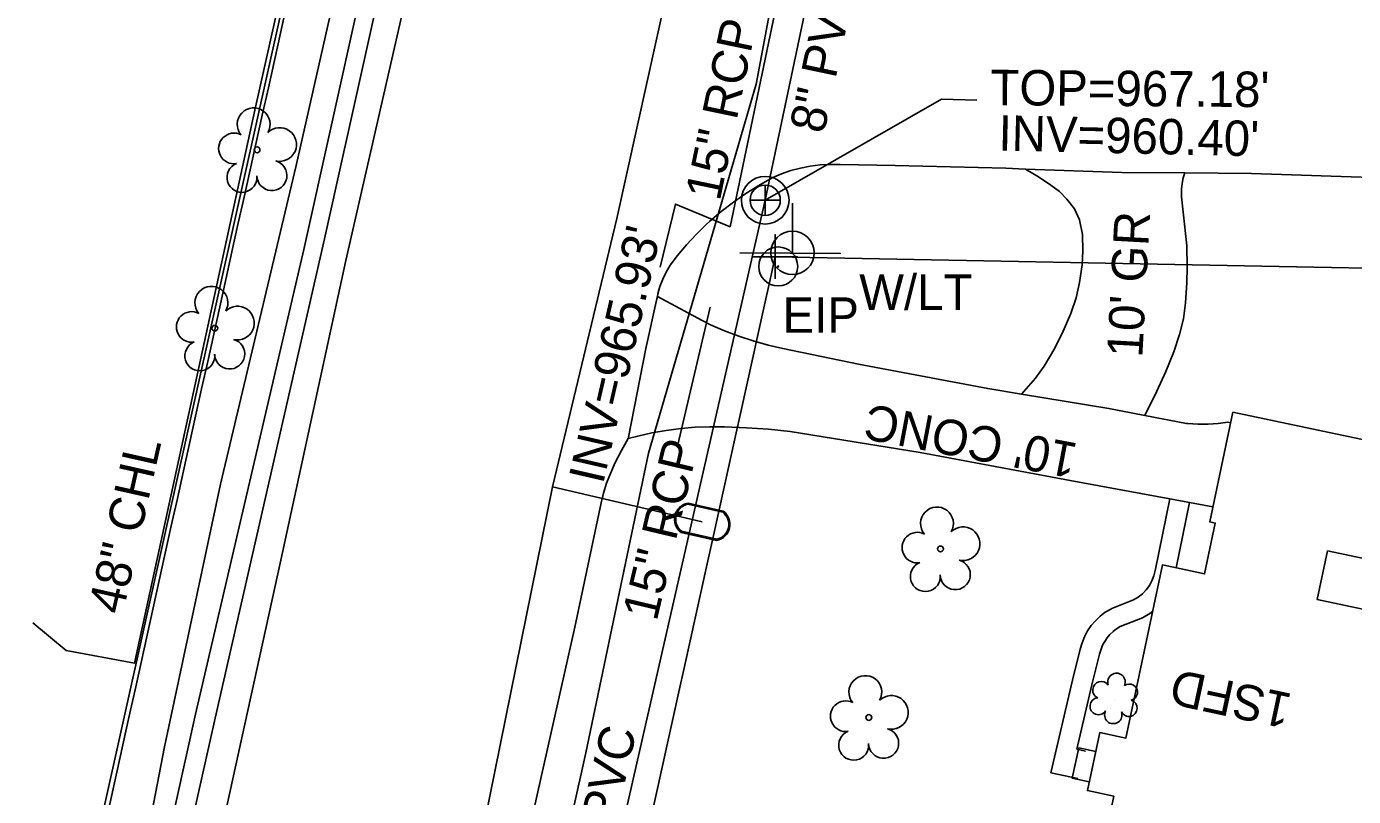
# Model space of a CAD drawing. Extents: x 1614611 to 1617571, y 898867 to 905462.
# Drawn here: x 1616262.4 to 1616412.2, y 900159.4 to 900246.3 of the extents above; entities that cross this region are included whole.
import ezdxf

# ---------------------------------------------------------------- set-up
doc = ezdxf.new("R2010")
doc.units = 0
for name, color, linetype in [('Exist Building', 7, 'Continuous'), ('Exist Building Text', 7, 'Continuous'), ('Exist Drainage Structure Drop Inlet CELL', 7, 'Continuous'), ('Exist Other Culture Area Outline', 7, 'Continuous'), ('Exist Other Culture Fence Line', 7, 'Continuous'), ('Exist Other Culture Fence Line Text', 7, 'Continuous'), ('Exist Other Culture Gate', 7, 'Continuous'), ('Exist Plan Preparation Watershed Yellow', 7, 'Continuous'), ('Exist Roads EOP Other Text', 7, 'Continuous'), ('Exist Roads Soil', 7, 'Continuous'), ('Exist Structure Minor Pipes RCP 15 Inch Invert', 7, 'Continuous'), ('Exist Utilities Gas UG Line SUE LOS B', 7, 'Continuous'), ('Exist Utilities Power Joint Use Telephone CELL', 7, 'Continuous'), ('Exist Utilities Power Pole Text', 7, 'Continuous'), ('Exist Utilities Sanitary Sewer AG Line Leader', 7, 'Continuous'), ('Exist Utilities Sanitary Sewer Manhole Text', 7, 'Continuous'), ('Exist Utilities Sanitary Sewer UG Line', 7, 'Continuous'), ('Exist Utilities Sanitary Sewer UG Line Invert Elevation', 7, 'Continuous'), ('Exist Utilities Sanitary Sewer UG Line Text', 7, 'Continuous'), ('Exist Utilities Telephone UG Cable SUE LOS B', 7, 'Continuous'), ('Exist Utilities Telephone UG Cable SUE LOS C', 7, 'Continuous'), ('Exist Utilities Telephone UG FO SUE LOS B', 7, 'Continuous'), ('Exist Utilities Telephone UG FO SUE LOS C', 7, 'Continuous'), ('Exist Utilities Water UG Line SUE LOS B', 7, 'Continuous'), ('Exist Vegetation Shrub CELL', 7, 'Continuous'), ('Exist Vegetation Tree CELL', 7, 'Continuous'), ('Old_Level_21', 7, 'Continuous'), ('Prop Drainage Structure Removal Label', 7, 'Continuous'), ('Prop Drainage Structure Tops and Inverts LABEL', 7, 'Continuous'), ('Prop Earthen Structure Head Ditch Label', 7, 'Continuous'), ('Prop Erosion Embankment Toe Protection with Rip Rap 2 Detail CELL', 7, 'Continuous'), ('Prop Plan Preparation Table Ditch Data CELL', 7, 'Continuous'), ('Prop SS Transition Line', 7, 'Continuous'), ('Scratch_Level_1', 7, 'Continuous'), ('Scratch_Level_9', 7, 'Continuous')]:
    doc.layers.add(name, color=color, linetype=linetype)

msp = doc.modelspace()

# ---------------------------------------------------------------- linework, layer by layer
at = {"layer": 'Exist Building'}
msp.add_lwpolyline([(1616398.62, 900202.81), (1616417.87, 900198.75), (1616415.15, 900185.89), (1616409.3, 900187.13), (1616408.14, 900181.65), (1616420.19, 900179.11), (1616414.27, 900151.09), (1616398.7, 900154.38), (1616397.06, 900146.63), (1616383.08, 900149.58), (1616385.16, 900159.46), (1616382.19, 900160.08), (1616383.58, 900166.63), (1616386.53, 900166.01), (1616390.66, 900185.56), (1616395.42, 900184.55), (1616396.63, 900190.28), (1616396, 900190.41)], close=True, dxfattribs=at)
at = {"layer": 'Exist Other Culture Area Outline'}
for points in [[(1616381.12, 900161.46), (1616378.07, 900162.09), (1616380.51, 900172.56), (1616381.39, 900176.06), (1616381.59, 900176.77), (1616381.86, 900177.45), (1616382.21, 900178.1), (1616382.62, 900178.7), (1616383.09, 900179.26), (1616383.63, 900179.77), (1616384.21, 900180.21), (1616384.84, 900180.58), (1616384.94, 900180.63), (1616387.41, 900181.6), (1616387.93, 900181.92), (1616388.41, 900182.3), (1616388.83, 900182.73), (1616389.19, 900183.22), (1616389.48, 900183.76), (1616389.7, 900184.32), (1616389.84, 900184.91), (1616389.87, 900185.06), (1616391.49, 900193.01)], [(1616392.2, 900185.23), (1616393.7, 900192.6)], [(1616381.97, 900164.54), (1616381.01, 900164.76), (1616382.7, 900172.03), (1616383.57, 900175.49), (1616383.73, 900176.05), (1616383.91, 900176.5), (1616384.14, 900176.93), (1616384.41, 900177.34), (1616384.73, 900177.71), (1616385.08, 900178.04), (1616385.47, 900178.33), (1616385.89, 900178.59), (1616388.41, 900179.57), (1616389.22, 900180.06), (1616389.56, 900180.34)], [(1616382.4, 900161.06), (1616380.48, 900161.48), (1616381.23, 900164.92), (1616383.13, 900164.51)]]:
    msp.add_lwpolyline(points, dxfattribs=at)
at = {"layer": 'Exist Other Culture Fence Line'}
msp.add_lwpolyline([(1616185.76, 900206.96), (1616171.64, 900210.69), (1616180.06, 900246.24), (1616199.38, 900333.73), (1616261.08, 900334.91), (1616309.42, 900336), (1616298.22, 900281.63), (1616288.21, 900236.88), (1616274.6, 900174.45), (1616266.9, 900175.88)], dxfattribs=at)
at = {"layer": 'Exist Other Culture Gate'}
msp.add_line((1616266.9, 900175.88), (1616263.14, 900179.03), dxfattribs=at)
at = {"layer": 'Exist Plan Preparation Watershed Yellow'}
for radius in [2.2, 0.0707]:
    msp.add_circle((1616347.28, 900219.25), radius, dxfattribs=at)
at = {"layer": 'Exist Roads Soil'}
for points in [[(1616374.75, 900204.84), (1616376.31, 900206.65), (1616377.3, 900208.01), (1616378.5, 900210.02), (1616379.44, 900211.93), (1616380.31, 900213.92), (1616380.92, 900215.69), (1616381.31, 900217.42), (1616381.58, 900219.45), (1616381.67, 900221.02), (1616381.62, 900222.87), (1616381.28, 900224.5), (1616380.73, 900225.74), (1616379.86, 900226.86), (1616379.02, 900227.7), (1616378.06, 900228.43), (1616376.67, 900229.35), (1616375.2, 900230.25)], [(1616388.66, 900202.44), (1616390.03, 900205.18), (1616391.06, 900207.38), (1616391.96, 900209.6), (1616392.59, 900211.55), (1616393.02, 900213.35), (1616393.26, 900215.13), (1616393.41, 900217.39), (1616393.45, 900219.16), (1616393.43, 900221.6), (1616393.01, 900225.37), (1616392.81, 900227.1), (1616392.8, 900227.96), (1616392.87, 900228.61), (1616392.99, 900229.25), (1616393.2, 900229.8)]]:
    msp.add_lwpolyline(points, dxfattribs=at)
at = {"layer": 'Exist Utilities Gas UG Line SUE LOS B'}
msp.add_lwpolyline([(1616228.95, 899933.49), (1616238.93, 899978.7), (1616250.88, 900021.2), (1616259.71, 900057.93), (1616268.22, 900097.82), (1616270.1, 900108.73), (1616270.66, 900110.37), (1616273.78, 900123.94), (1616283.72, 900168.25), (1616296.04, 900222.38), (1616305.4, 900264.37), (1616315.91, 900311.24), (1616322.64, 900340.02), (1616331.7, 900383.47)], dxfattribs=at)
at = {"layer": 'Exist Utilities Power Joint Use Telephone CELL'}
msp.add_line((1616348.88, 900220.77), (1616348.88, 900220.77), dxfattribs=at)
msp.add_lwpolyline([(1616342.95, 900220.77), (1616354.28, 900220.73), (1616348.88, 900220.75), (1616348.88, 900226.39)], dxfattribs=at)
msp.add_circle((1616348.89, 900220.78), 2.45, dxfattribs=at)
at = {"layer": 'Exist Utilities Sanitary Sewer AG Line Leader'}
msp.add_lwpolyline([(1616345.82, 900226.73), (1616365.72, 900238.14), (1616369.69, 900238.01)], dxfattribs=at)
at = {"layer": 'Exist Utilities Sanitary Sewer UG Line'}
msp.add_lwpolyline([(1616305.43, 900049.6), (1616345.82, 900226.73), (1616377.74, 900378.04)], dxfattribs=at)
at = {"layer": 'Exist Utilities Telephone UG Cable SUE LOS B'}
msp.add_lwpolyline([(1616244.2, 900051.3), (1616247.08, 900051.95), (1616254.34, 900051.12), (1616261.35, 900056.95), (1616270.62, 900097.78), (1616272.63, 900108.4), (1616271.69, 900124.33), (1616281.5, 900168.7), (1616293.72, 900221.15), (1616303.1, 900263.43), (1616314, 900311.75), (1616319.02, 900336.01), (1616313.74, 900338.14), (1616311.89, 900339.38)], dxfattribs=at)
at = {"layer": 'Exist Utilities Telephone UG Cable SUE LOS C'}
msp.add_lwpolyline([(1616244.2, 900051.3), (1616248.43, 900052.69), (1616253.12, 900054.18), (1616256.06, 900055.79), (1616257.99, 900061.57), (1616266.68, 900088.03), (1616271.15, 900108.67), (1616270.12, 900124.07), (1616271.06, 900129.11), (1616277.99, 900165.03), (1616284.33, 900194.68), (1616292.87, 900230.63), (1616300.4, 900263.94), (1616307.49, 900293.65), (1616316.18, 900332.48), (1616316.31, 900333.6), (1616315.2, 900335.07), (1616313.08, 900336.87), (1616311.89, 900339.38)], dxfattribs=at)
at = {"layer": 'Exist Utilities Telephone UG FO SUE LOS B'}
msp.add_lwpolyline([(1616264.27, 899888.11), (1616275.63, 899938.03), (1616283.17, 899975.46), (1616294.6, 900026.16), (1616305.05, 900073.25), (1616315.15, 900117.57), (1616325.55, 900164.34), (1616332.62, 900198.17), (1616344.78, 900239.81), (1616353.34, 900285.35), (1616361.31, 900327.32), (1616372.74, 900375.18)], dxfattribs=at)
at = {"layer": 'Exist Utilities Telephone UG FO SUE LOS C'}
msp.add_line((1616246.03, 900045.13), (1616403.99, 900755.27), dxfattribs=at)
at = {"layer": 'Exist Utilities Water UG Line SUE LOS B'}
msp.add_line((1616321.8, 900194.38), (1616338.71, 900190.42), dxfattribs=at)
msp.add_lwpolyline([(1616263.66, 899921.5), (1616269.73, 899949.09), (1616273.73, 899969.37), (1616281.36, 900005.29), (1616288.43, 900036.76), (1616298.97, 900086.16), (1616304.15, 900111.94), (1616312.34, 900147.74), (1616321.8, 900194.38), (1616329.08, 900224.67), (1616335.91, 900255.64), (1616338.25, 900266.44), (1616344.58, 900294.92), (1616354.08, 900334.27), (1616364.03, 900380.59)], dxfattribs=at)
at = {"layer": 'Exist Vegetation Shrub CELL'}
msp.add_line((1616385.24, 900170.31), (1616385.24, 900170.31), dxfattribs=at)
for centre, radius, start, end in [((1616385.47, 900172.35), 0.99, 334.8391, 200.4717), ((1616383.76, 900171.43), 0.968, 35.8908, 245.4216), ((1616386.91, 900171.18), 0.929, 284.4567, 126.0861), ((1616383.44, 900169.6), 0.955, 95.1099, 327.9534), ((1616386.88, 900169.38), 0.937, 204.9913, 73.4601), ((1616385.11, 900168.62), 0.984, 151.2797, 21.387)]:
    msp.add_arc(centre, radius, start, end, dxfattribs=at)
at = {"layer": 'Exist Vegetation Tree CELL'}
for p, q in [((1616288.45, 900232.42), (1616288.45, 900232.42)), ((1616283.68, 900212.27), (1616283.68, 900212.27)), ((1616365.6, 900187.36), (1616365.6, 900187.36)), ((1616357.51, 900168.33), (1616357.51, 900168.33))]:
    msp.add_line(p, q, dxfattribs=at)
for centre in [(1616288.45, 900232.42), (1616283.68, 900212.27), (1616365.6, 900187.36), (1616357.51, 900168.33)]:
    msp.add_circle(centre, 0.326, dxfattribs=at)
for centre, radius, start, end in [((1616288.06, 900235.29), 1.86, 330.1651, 219.7134), ((1616291, 900233.01), 1.9, 257.1011, 134.1999), ((1616285.84, 900232.57), 1.73, 62.6636, 279.3457), ((1616286.74, 900229.3), 1.69, 111.5671, 6.231), ((1616290.12, 900229.52), 1.7, 181.2822, 74.56), ((1616283.29, 900215.14), 1.86, 330.1651, 219.7134), ((1616281.07, 900212.42), 1.73, 62.6636, 279.3457), ((1616286.23, 900212.86), 1.9, 257.1011, 134.1999), ((1616281.98, 900209.15), 1.69, 111.5671, 6.231), ((1616285.35, 900209.37), 1.7, 181.2822, 74.56), ((1616365.21, 900190.23), 1.86, 330.1651, 219.7134), ((1616368.15, 900187.95), 1.9, 257.1011, 134.1999), ((1616362.99, 900187.51), 1.73, 62.6636, 279.3457), ((1616363.89, 900184.24), 1.69, 111.5671, 6.231), ((1616367.27, 900184.46), 1.7, 181.2822, 74.56), ((1616357.12, 900171.2), 1.86, 330.1651, 219.7134), ((1616354.9, 900168.48), 1.73, 62.6636, 279.3457), ((1616360.06, 900168.91), 1.9, 257.1011, 134.1999), ((1616359.18, 900165.43), 1.7, 181.2822, 74.56), ((1616355.8, 900165.2), 1.69, 111.5671, 6.231)]:
    msp.add_arc(centre, radius, start, end, dxfattribs=at)
at = {"layer": 'Old_Level_21'}
msp.add_lwpolyline([(1616345.81, 900228.44), (1616345.81, 900225.02), (1616345.81, 900226.73), (1616347.52, 900226.73), (1616344.09, 900226.73)], dxfattribs=at)
for radius in [2.69, 1.71]:
    msp.add_circle((1616345.81, 900226.73), radius, dxfattribs=at)
at = {"layer": 'Prop Drainage Structure Removal Label'}
msp.add_lwpolyline([(1616341.86, 900223.71), (1616335.68, 900226.29), (1616333.94, 900219.17)], dxfattribs=at)
at = {"layer": 'Prop Drainage Structure Tops and Inverts LABEL'}
msp.add_line((1616346.95, 900220.35), (1616346.95, 900220.35), dxfattribs=at)
msp.add_lwpolyline([(1616344.45, 900220.35), (1616349.45, 900220.35), (1616346.95, 900220.35), (1616346.95, 900222.85), (1616346.95, 900217.85)], dxfattribs=at)
at = {"layer": 'Prop Earthen Structure Head Ditch Label'}
msp.add_line((1616346.95, 900220.35), (1616622.33, 900214.99), dxfattribs=at)
for radius, start, end in [(100030, 167.4537079, 167.5697278), (99970, 167.4989737, 167.7161189)]:
    msp.add_arc((1713946.87, 878581.13), radius, start, end, dxfattribs=at)
at = {"layer": 'Prop Plan Preparation Table Ditch Data CELL'}
for p, q in [((1616349.29, 900259.43), (1616341.86, 900223.71)), ((1616339.61, 900214.66), (1616335.9, 900198.98))]:
    msp.add_line(p, q, dxfattribs=at)
at = {"layer": 'Prop SS Transition Line'}
msp.add_line((1616338.71, 900190.42), (1616338.71, 900190.42), dxfattribs=at)
for points in [[(1616337.1, 900192.53), (1616341.07, 900191.63)], [(1616337.07, 900192.4), (1616341.04, 900191.5)], [(1616340.32, 900188.32), (1616336.32, 900189.22)], [(1616340.35, 900188.45), (1616336.35, 900189.36)]]:
    msp.add_lwpolyline(points, dxfattribs=at)
for centre, radius, start, end in [((1616337.43, 900190.71), 1.86, 100.4278, 233.2292), ((1616337.44, 900190.71), 1.73, 102.5507, 231.0321), ((1616339.97, 900190.14), 1.86, 280.8981, 53.5581), ((1616339.98, 900190.14), 1.73, 282.3769, 52.1226)]:
    msp.add_arc(centre, radius, start, end, dxfattribs=at)
at = {"layer": 'Scratch_Level_1'}
for points in [[(1616398.37, 900201.6), (1616398.06, 900201.67), (1616396.94, 900201.51), (1616395.81, 900201.43), (1616394.67, 900201.43), (1616393.54, 900201.51), (1616393.36, 900201.53), (1616388.66, 900202.44), (1616384.61, 900203.23), (1616374.75, 900204.84), (1616370.94, 900205.46), (1616356.35, 900208.23), (1616347.8, 900210), (1616346.13, 900210.38), (1616344.47, 900210.84), (1616342.83, 900211.38), (1616341.22, 900211.99), (1616339.65, 900212.67), (1616338.68, 900213.13), (1616333.64, 900215.87)], [(1616396.36, 900192.1), (1616393.7, 900192.6), (1616391.49, 900193.01), (1616380.26, 900195.09), (1616363.29, 900198.25), (1616348.64, 900200.62), (1616346.18, 900200.87), (1616343.71, 900201.05), (1616341.23, 900201.14), (1616339.56, 900201.16), (1616337.92, 900201.09), (1616336.28, 900200.95), (1616334.65, 900200.73), (1616333.02, 900200.45), (1616331.42, 900200.1), (1616330.34, 900199.82)]]:
    msp.add_lwpolyline(points, dxfattribs=at)
at = {"layer": 'Scratch_Level_9'}
for points in [[(1616277.78, 900124.91), (1616283.67, 900152.17), (1616291.12, 900186.08), (1616298.45, 900219.92), (1616305.64, 900251.41), (1616313.34, 900285.67), (1616320.34, 900318.08), (1616327.24, 900348.71), (1616334.4, 900380.72), (1616342.13, 900414.51), (1616348.75, 900444.16), (1616354.62, 900470.67), (1616359.82, 900493.8), (1616362.54, 900506.97)], [(1616415.37, 900229.27), (1616400.73, 900229.73), (1616393.2, 900229.8), (1616386.06, 900229.87), (1616375.2, 900230.25), (1616372.98, 900230.33), (1616360.5, 900230.63), (1616354.27, 900230.75), (1616353.15, 900230.77), (1616352.02, 900230.71), (1616350.9, 900230.58), (1616349.8, 900230.36), (1616348.71, 900230.07), (1616347.64, 900229.7), (1616346.6, 900229.25), (1616346.6, 900229.25), (1616345.1, 900228.4), (1616343.64, 900227.48), (1616342.22, 900226.49), (1616340.85, 900225.44), (1616339.53, 900224.33), (1616339.15, 900223.99), (1616338.02, 900222.87), (1616336.94, 900221.7), (1616335.91, 900220.47), (1616335.09, 900219.38), (1616334.63, 900218.62), (1616334.25, 900217.83), (1616333.93, 900217), (1616333.69, 900216.14), (1616333.64, 900215.87), (1616333.59, 900215.6), (1616332.33, 900210), (1616330.37, 900199.99), (1616330.34, 900199.82), (1616329.58, 900198.49), (1616328.89, 900197.13), (1616328.34, 900195.89), (1616327.91, 900194.78), (1616327.55, 900193.64), (1616327.28, 900192.57), (1616324.33, 900178.53), (1616318.14, 900151.05)]]:
    msp.add_lwpolyline(points, dxfattribs=at)

# ---------------------------------------------------------------- texts
at = {"layer": 'Exist Building Text'}
msp.add_text('1SFD', height=4, rotation=167.9641, dxfattribs=at).set_placement((1616405.46, 900170.96))
at = {"layer": 'Exist Drainage Structure Drop Inlet CELL'}
msp.add_text('EIP', height=4, dxfattribs=at).set_placement((1616347.77, 900211.76))
at = {"layer": 'Exist Other Culture Fence Line Text'}
msp.add_text('48" CHL', height=4, rotation=77.3347, dxfattribs=at).set_placement((1616273.26, 900179.84))
at = {"layer": 'Exist Roads EOP Other Text'}
for s, rotation, p in [("10' GR", 86.88, (1616388.38, 900208.9)), ("10' CONC", 169.2367, (1616381.26, 900199.23))]:
    msp.add_text(s, height=4, rotation=rotation, dxfattribs=at).set_placement(p)
at = {"layer": 'Exist Structure Minor Pipes RCP 15 Inch Invert'}
msp.add_text("INV=965.93'", height=4, rotation=77.0124, dxfattribs=at).set_placement((1616327.5, 900194.56))
at = {"layer": 'Exist Utilities Power Pole Text'}
msp.add_text('W/LT', height=4, dxfattribs=at).set_placement((1616356.43, 900214.35))
at = {"layer": 'Exist Utilities Sanitary Sewer Manhole Text'}
msp.add_text("TOP=967.18'", height=4, rotation=359.5785, dxfattribs=at).set_placement((1616371.23, 900237.46))
at = {"layer": 'Exist Utilities Sanitary Sewer UG Line Invert Elevation'}
msp.add_text("INV=960.40'", height=4, rotation=358.6965, dxfattribs=at).set_placement((1616372.12, 900232.34))
at = {"layer": 'Exist Utilities Sanitary Sewer UG Line Text'}
for rotation, p in [(78.0873, (1616352.44, 900234.12)), (77.1562, (1616327.46, 900149.93))]:
    msp.add_text('8" PVC', height=4, rotation=rotation, dxfattribs=at).set_placement(p)
at = {"layer": 'Prop Erosion Embankment Toe Protection with Rip Rap 2 Detail CELL'}
for rotation, p in [(78.2456, (1616340.68, 900226.53)), (76.6625, (1616333.55, 900179.1))]:
    msp.add_text('15" RCP', height=4, rotation=rotation, dxfattribs=at).set_placement(p)

doc.saveas('drawing.dxf')
